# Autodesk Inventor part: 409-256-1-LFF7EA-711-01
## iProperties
Created: 2010-06
Part Number: 409-256-1-LFF7EA-711-01
Material: Sch40 CS PIPE SEAMLESS
Description: PIPE
Document SubType Name: Modeling
Designer: S. Boerckel
Engineer: Steve Boerckel
Mass: 4083.05 g
Surface Area: 1769.03 cm^2
Volume: 520.133 cm^3
Density: 7.85 g/cm^3
Cost Center: 4"
SMR: =<COST CENTER> - <Material>
Length: 10.000 in
Title: 3"
Author: S. Boerckel
Revision Number: A
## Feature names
1. Extrusion1
